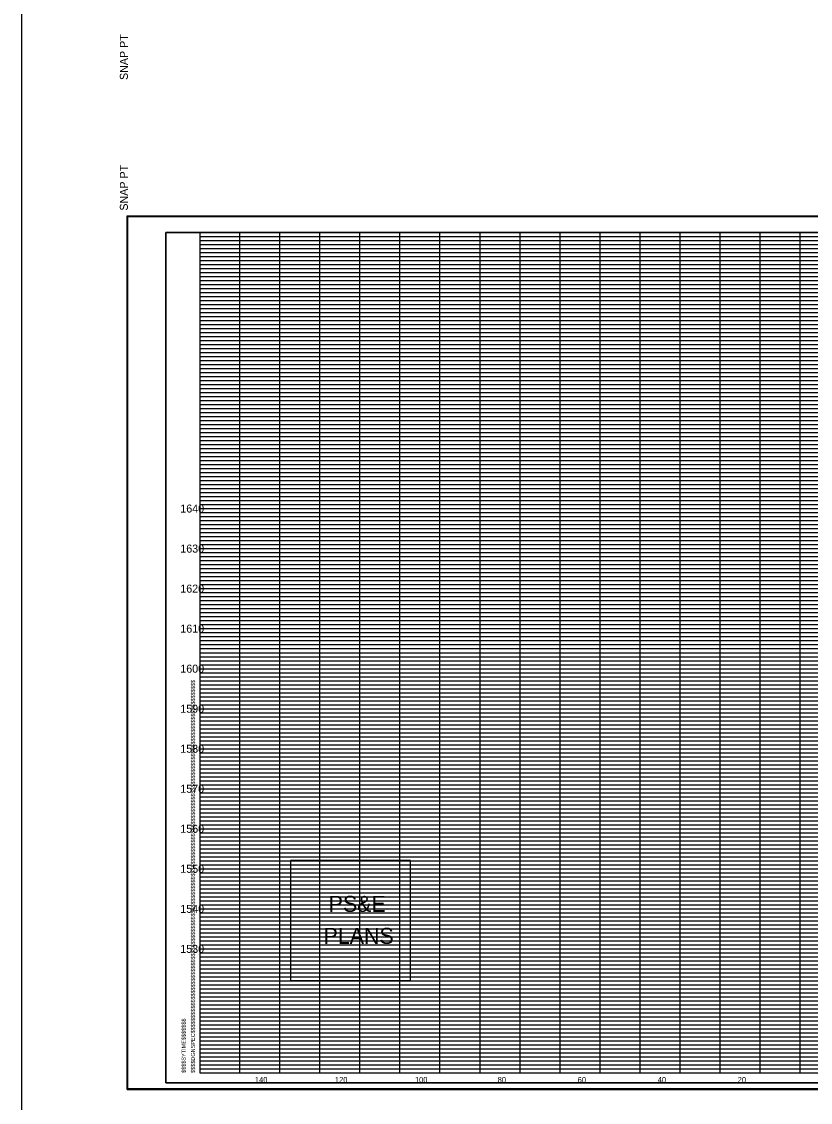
# Model space of a CAD drawing. Extents: x 955 to 1375, y 1248 to 3657.
# Drawn here: x 955.4 to 1152.6, y 2072.7 to 2342.7 of the extents above; entities that cross this region are included whole.
import ezdxf

# ---------------------------------------------------------------- set-up
doc = ezdxf.new("R2010")
doc.units = 0
for name, color, linetype in [('DESIGN - SHEET - Corner Text', 7, 'Continuous'), ('DESIGN - SHEET - Light Grid', 7, 'Continuous'), ('DESIGN - SHEET - Linework', 7, 'Continuous'), ('DESIGN - SHEET - Plot Shape', 7, 'Continuous'), ('DESIGN - TYPICAL - Text', 7, 'Continuous'), ('DESIGN - UTILITIES - Cable (Overhead) with Text', 7, 'Continuous'), ('SURVEY - NON-TRANSPORTATION - Features Text', 7, 'Continuous')]:
    doc.layers.add(name, color=color, linetype=linetype)

# ---------------------------------------------------------------- blocks, each defined once
blk = doc.blocks.new('XSTSHT')
at = {"layer": 'DESIGN - SHEET - Light Grid'}
for p, q in [((0, 20.9), (8, 20.9)), ((0, 20.8), (8, 20.8)), ((8, 20.9), (16, 20.9)), ((8, 20.8), (16, 20.8)), ((0, 20.7), (8, 20.7)), ((0, 20.6), (8, 20.6)), ((8, 20.7), (16, 20.7)), ((8, 20.6), (16, 20.6)), ((0, 20.5), (8, 20.5)), ((0, 20.4), (8, 20.4)), ((0, 20.3), (8, 20.3)), ((8, 20.5), (16, 20.5)), ((8, 20.4), (16, 20.4)), ((8, 20.3), (16, 20.3)), ((0, 20.2), (8, 20.2)), ((0, 20.1), (8, 20.1)), ((8, 20.2), (16, 20.2)), ((8, 20.1), (16, 20.1)), ((0, 19.9), (8, 19.9)), ((0, 19.8), (8, 19.8)), ((8, 19.9), (16, 19.9)), ((8, 19.8), (16, 19.8)), ((0, 19.7), (8, 19.7)), ((0, 19.6), (8, 19.6)), ((0, 19.5), (8, 19.5)), ((8, 19.7), (16, 19.7)), ((8, 19.6), (16, 19.6)), ((8, 19.5), (16, 19.5)), ((0, 19.4), (8, 19.4)), ((0, 19.3), (8, 19.3)), ((0, 19.2), (8, 19.2)), ((8, 19.4), (16, 19.4)), ((8, 19.3), (16, 19.3)), ((8, 19.2), (16, 19.2)), ((0, 19.1), (8, 19.1)), ((0, 18.9), (8, 18.9)), ((8, 19.1), (16, 19.1)), ((8, 18.9), (16, 18.9)), ((0, 18.8), (8, 18.8)), ((0, 18.7), (8, 18.7)), ((8, 18.8), (16, 18.8)), ((8, 18.7), (16, 18.7)), ((0, 18.6), (8, 18.6)), ((0, 18.5), (8, 18.5)), ((0, 18.4), (8, 18.4)), ((8, 18.6), (16, 18.6)), ((8, 18.5), (16, 18.5)), ((8, 18.4), (16, 18.4)), ((0, 18.3), (8, 18.3)), ((0, 18.2), (8, 18.2)), ((0, 18.1), (8, 18.1)), ((8, 18.3), (16, 18.3)), ((8, 18.2), (16, 18.2)), ((8, 18.1), (16, 18.1)), ((0, 17.9), (8, 17.9)), ((8, 17.9), (16, 17.9)), ((0, 17.8), (8, 17.8)), ((0, 17.7), (8, 17.7)), ((0, 17.6), (8, 17.6)), ((8, 17.8), (16, 17.8)), ((8, 17.7), (16, 17.7)), ((8, 17.6), (16, 17.6)), ((0, 17.5), (8, 17.5)), ((0, 17.4), (8, 17.4)), ((0, 17.3), (8, 17.3)), ((8, 17.5), (16, 17.5)), ((8, 17.4), (16, 17.4)), ((8, 17.3), (16, 17.3)), ((0, 17.2), (8, 17.2)), ((0, 17.1), (8, 17.1)), ((8, 17.2), (16, 17.2)), ((8, 17.1), (16, 17.1)), ((0, 16.9), (8, 16.9)), ((0, 16.8), (8, 16.8)), ((8, 16.9), (16, 16.9)), ((8, 16.8), (16, 16.8)), ((0, 16.7), (8, 16.7)), ((0, 16.6), (8, 16.6)), ((0, 16.5), (8, 16.5)), ((8, 16.7), (16, 16.7)), ((8, 16.6), (16, 16.6)), ((8, 16.5), (16, 16.5)), ((0, 16.4), (8, 16.4)), ((0, 16.3), (8, 16.3)), ((8, 16.4), (16, 16.4)), ((8, 16.3), (16, 16.3)), ((0, 16.2), (8, 16.2)), ((0, 16.1), (8, 16.1)), ((8, 16.2), (16, 16.2)), ((8, 16.1), (16, 16.1)), ((0, 15.9), (8, 15.9)), ((0, 15.8), (8, 15.8)), ((0, 15.7), (8, 15.7)), ((8, 15.9), (16, 15.9)), ((8, 15.8), (16, 15.8)), ((8, 15.7), (16, 15.7)), ((0, 15.6), (8, 15.6)), ((0, 15.5), (8, 15.5)), ((0, 15.4), (8, 15.4)), ((8, 15.6), (16, 15.6)), ((8, 15.5), (16, 15.5)), ((8, 15.4), (16, 15.4)), ((0, 15.3), (8, 15.3)), ((0, 15.2), (8, 15.2)), ((8, 15.3), (16, 15.3)), ((8, 15.2), (16, 15.2)), ((0, 15.1), (8, 15.1)), ((0, 14.9), (8, 14.9)), ((8, 15.1), (16, 15.1)), ((8, 14.9), (16, 14.9)), ((0, 14.8), (8, 14.8)), ((0, 14.7), (8, 14.7)), ((0, 14.6), (8, 14.6)), ((8, 14.8), (16, 14.8)), ((8, 14.7), (16, 14.7)), ((8, 14.6), (16, 14.6)), ((0, 14.5), (8, 14.5)), ((0, 14.4), (8, 14.4)), ((8, 14.5), (16, 14.5)), ((8, 14.4), (16, 14.4)), ((0, 14.3), (8, 14.3)), ((0, 14.2), (8, 14.2)), ((0, 14.1), (8, 14.1)), ((8, 14.3), (16, 14.3)), ((8, 14.2), (16, 14.2)), ((8, 14.1), (16, 14.1)), ((0, 13.9), (8, 13.9)), ((0, 13.8), (8, 13.8)), ((8, 13.9), (16, 13.9)), ((8, 13.8), (16, 13.8)), ((0, 13.7), (8, 13.7)), ((0, 13.6), (8, 13.6)), ((0, 13.5), (8, 13.5)), ((8, 13.7), (16, 13.7)), ((8, 13.6), (16, 13.6)), ((8, 13.5), (16, 13.5)), ((0, 13.4), (8, 13.4)), ((0, 13.3), (8, 13.3)), ((8, 13.4), (16, 13.4)), ((8, 13.3), (16, 13.3)), ((0, 13.2), (8, 13.2)), ((0, 13.1), (8, 13.1)), ((8, 13.2), (16, 13.2)), ((8, 13.1), (16, 13.1)), ((0, 12.9), (8, 12.9)), ((0, 12.8), (8, 12.8)), ((0, 12.7), (8, 12.7)), ((8, 12.9), (16, 12.9)), ((8, 12.8), (16, 12.8)), ((8, 12.7), (16, 12.7)), ((0, 12.6), (8, 12.6)), ((0, 12.5), (8, 12.5)), ((8, 12.6), (16, 12.6)), ((8, 12.5), (16, 12.5)), ((0, 12.4), (8, 12.4)), ((0, 12.3), (8, 12.3)), ((0, 12.2), (8, 12.2)), ((8, 12.4), (16, 12.4)), ((8, 12.3), (16, 12.3)), ((8, 12.2), (16, 12.2)), ((0, 12.1), (8, 12.1)), ((0, 11.9), (8, 11.9)), ((8, 12.1), (16, 12.1)), ((8, 11.9), (16, 11.9)), ((0, 11.8), (8, 11.8)), ((0, 11.7), (8, 11.7)), ((8, 11.8), (16, 11.8)), ((8, 11.7), (16, 11.7)), ((0, 11.6), (8, 11.6)), ((0, 11.5), (8, 11.5)), ((0, 11.4), (8, 11.4)), ((8, 11.6), (16, 11.6)), ((8, 11.5), (16, 11.5)), ((8, 11.4), (16, 11.4)), ((0, 11.3), (8, 11.3)), ((0, 11.2), (8, 11.2)), ((0, 11.1), (8, 11.1)), ((8, 11.3), (16, 11.3)), ((8, 11.2), (16, 11.2)), ((8, 11.1), (16, 11.1)), ((0, 10.9), (8, 10.9)), ((0, 10.8), (8, 10.8)), ((8, 10.9), (16, 10.9)), ((8, 10.8), (16, 10.8)), ((0, 10.7), (8, 10.7)), ((0, 10.6), (8, 10.6)), ((8, 10.7), (16, 10.7)), ((8, 10.6), (16, 10.6)), ((0, 10.5), (8, 10.5)), ((0, 10.4), (8, 10.4)), ((0, 10.3), (8, 10.3)), ((8, 10.5), (16, 10.5)), ((8, 10.4), (16, 10.4)), ((8, 10.3), (16, 10.3)), ((0, 10.2), (8, 10.2)), ((0, 10.1), (8, 10.1)), ((8, 10.2), (16, 10.2)), ((8, 10.1), (16, 10.1)), ((0, 9.9), (8, 9.9)), ((0, 9.8), (8, 9.8)), ((8, 9.9), (16, 9.9)), ((8, 9.8), (16, 9.8)), ((0, 9.7), (8, 9.7)), ((0, 9.6), (8, 9.6)), ((0, 9.5), (8, 9.5)), ((8, 9.7), (16, 9.7)), ((8, 9.6), (16, 9.6)), ((8, 9.5), (16, 9.5)), ((0, 9.4), (8, 9.4)), ((0, 9.3), (8, 9.3)), ((0, 9.2), (8, 9.2)), ((8, 9.4), (16, 9.4)), ((8, 9.3), (16, 9.3)), ((8, 9.2), (16, 9.2)), ((0, 9.1), (8, 9.1)), ((8, 9.1), (16, 9.1)), ((0, 8.9), (8, 8.9)), ((0, 8.8), (8, 8.8)), ((0, 8.7), (8, 8.7)), ((8, 8.9), (16, 8.9)), ((8, 8.8), (16, 8.8)), ((8, 8.7), (16, 8.7)), ((0, 8.6), (8, 8.6)), ((0, 8.5), (8, 8.5)), ((0, 8.4), (8, 8.4)), ((8, 8.6), (16, 8.6)), ((8, 8.5), (16, 8.5)), ((8, 8.4), (16, 8.4)), ((0, 8.3), (8, 8.3)), ((0, 8.2), (8, 8.2)), ((8, 8.3), (16, 8.3)), ((8, 8.2), (16, 8.2)), ((0, 8.1), (8, 8.1)), ((0, 7.9), (8, 7.9)), ((8, 8.1), (16, 8.1)), ((8, 7.9), (16, 7.9)), ((0, 7.8), (8, 7.8)), ((0, 7.7), (8, 7.7)), ((0, 7.6), (8, 7.6)), ((8, 7.8), (16, 7.8)), ((8, 7.7), (16, 7.7)), ((8, 7.6), (16, 7.6)), ((0, 7.5), (8, 7.5)), ((0, 7.4), (8, 7.4)), ((0, 7.3), (8, 7.3)), ((8, 7.5), (16, 7.5)), ((8, 7.4), (16, 7.4)), ((8, 7.3), (16, 7.3)), ((0, 7.2), (8, 7.2)), ((0, 7.1), (8, 7.1)), ((8, 7.2), (16, 7.2)), ((8, 7.1), (16, 7.1)), ((0, 6.9), (8, 6.9)), ((0, 6.8), (8, 6.8)), ((8, 6.9), (16, 6.9)), ((8, 6.8), (16, 6.8)), ((0, 6.7), (8, 6.7)), ((0, 6.6), (8, 6.6)), ((0, 6.5), (8, 6.5)), ((8, 6.7), (16, 6.7)), ((8, 6.6), (16, 6.6)), ((8, 6.5), (16, 6.5)), ((0, 6.4), (8, 6.4)), ((0, 6.3), (8, 6.3)), ((8, 6.4), (16, 6.4)), ((8, 6.3), (16, 6.3)), ((0, 6.2), (8, 6.2)), ((0, 6.1), (8, 6.1)), ((8, 6.2), (16, 6.2)), ((8, 6.1), (16, 6.1)), ((0, 5.9), (8, 5.9)), ((0, 5.8), (8, 5.8)), ((0, 5.7), (8, 5.7)), ((8, 5.9), (16, 5.9)), ((8, 5.8), (16, 5.8)), ((8, 5.7), (16, 5.7)), ((0, 5.6), (8, 5.6)), ((0, 5.5), (8, 5.5)), ((0, 5.4), (8, 5.4)), ((8, 5.6), (16, 5.6)), ((8, 5.5), (16, 5.5)), ((8, 5.4), (16, 5.4)), ((0, 5.3), (8, 5.3)), ((0, 5.2), (8, 5.2)), ((8, 5.3), (16, 5.3)), ((8, 5.2), (16, 5.2)), ((0, 5.1), (8, 5.1)), ((0, 4.9), (8, 4.9)), ((8, 5.1), (16, 5.1)), ((8, 4.9), (16, 4.9)), ((0, 4.8), (8, 4.8)), ((0, 4.7), (8, 4.7)), ((0, 4.6), (8, 4.6)), ((8, 4.8), (16, 4.8)), ((8, 4.7), (16, 4.7)), ((8, 4.6), (16, 4.6)), ((0, 4.5), (8, 4.5)), ((0, 4.4), (8, 4.4)), ((8, 4.5), (16, 4.5)), ((8, 4.4), (16, 4.4)), ((0, 4.3), (8, 4.3)), ((0, 4.2), (8, 4.2)), ((0, 4.1), (8, 4.1)), ((8, 4.3), (16, 4.3)), ((8, 4.2), (16, 4.2)), ((8, 4.1), (16, 4.1)), ((0, 3.9), (8, 3.9)), ((0, 3.8), (8, 3.8)), ((8, 3.9), (16, 3.9)), ((8, 3.8), (16, 3.8)), ((0, 3.7), (8, 3.7)), ((0, 3.6), (8, 3.6)), ((8, 3.7), (16, 3.7)), ((8, 3.6), (16, 3.6)), ((0, 3.5), (8, 3.5)), ((0, 3.4), (8, 3.4)), ((0, 3.3), (8, 3.3)), ((8, 3.5), (16, 3.5)), ((8, 3.4), (16, 3.4)), ((8, 3.3), (16, 3.3)), ((0, 3.2), (8, 3.2)), ((0, 3.1), (8, 3.1)), ((8, 3.2), (16, 3.2)), ((8, 3.1), (16, 3.1)), ((0, 2.9), (8, 2.9)), ((0, 2.8), (8, 2.8)), ((0, 2.7), (8, 2.7)), ((8, 2.9), (16, 2.9)), ((8, 2.8), (16, 2.8)), ((8, 2.7), (16, 2.7)), ((0, 2.6), (8, 2.6)), ((0, 2.5), (8, 2.5)), ((8, 2.6), (16, 2.6)), ((8, 2.5), (16, 2.5)), ((0, 2.4), (8, 2.4)), ((0, 2.3), (8, 2.3)), ((0, 2.2), (8, 2.2)), ((8, 2.4), (16, 2.4)), ((8, 2.3), (16, 2.3)), ((8, 2.2), (16, 2.2)), ((0, 2.1), (8, 2.1)), ((0, 1.9), (8, 1.9)), ((8, 2.1), (16, 2.1)), ((8, 1.9), (16, 1.9)), ((0, 1.8), (8, 1.8)), ((0, 1.7), (8, 1.7)), ((8, 1.8), (16, 1.8)), ((8, 1.7), (16, 1.7)), ((0, 1.6), (8, 1.6)), ((0, 1.5), (8, 1.5)), ((0, 1.4), (8, 1.4)), ((8, 1.6), (16, 1.6)), ((8, 1.5), (16, 1.5)), ((8, 1.4), (16, 1.4)), ((0, 1.3), (8, 1.3)), ((0, 1.2), (8, 1.2)), ((0, 1.1), (8, 1.1)), ((8, 1.3), (16, 1.3)), ((8, 1.2), (16, 1.2)), ((8, 1.1), (16, 1.1)), ((0, 0.9), (8, 0.9)), ((8, 0.9), (16, 0.9)), ((0, 0.8), (8, 0.8)), ((0, 0.7), (8, 0.7)), ((0, 0.6), (8, 0.6)), ((8, 0.8), (16, 0.8)), ((8, 0.7), (16, 0.7)), ((8, 0.6), (16, 0.6)), ((0, 0.5), (8, 0.5)), ((0, 0.4), (8, 0.4)), ((0, 0.3), (8, 0.3)), ((8, 0.5), (16, 0.5)), ((8, 0.4), (16, 0.4)), ((8, 0.3), (16, 0.3)), ((0, 0.2), (8, 0.2)), ((0, 0.1), (8, 0.1)), ((8, 0.2), (16, 0.2)), ((8, 0.1), (16, 0.1))]:
    blk.add_line(p, q, dxfattribs=at)
at = {"layer": 'DESIGN - SHEET - Linework'}
for p, q in [((-1.823, -0.414), (-1.823, 21.414)), ((-1.823, 21.414), (32.217, 21.414)), ((1, 0), (1, 21)), ((2, 0), (2, 21)), ((3, 0), (3, 21)), ((4, 0), (4, 21)), ((5, 0), (5, 21)), ((6, 0), (6, 21)), ((7, 0), (7, 21)), ((8, 0), (8, 21)), ((9, 0), (9, 21)), ((10, 0), (10, 21)), ((11, 0), (11, 21)), ((12, 0), (12, 21)), ((13, 0), (13, 21)), ((14, 0), (14, 21)), ((15, 0), (15, 21)), ((0, 20), (28, 20)), ((0, 19), (32, 19)), ((0, 18), (32, 18)), ((0, 17), (32, 17)), ((0, 16), (32, 16)), ((0, 15), (32, 15)), ((0, 14), (32, 14)), ((0, 13), (32, 13)), ((0, 12), (32, 12)), ((0, 11), (32, 11)), ((0, 10), (32, 10)), ((0, 9), (32, 9)), ((0, 8), (32, 8)), ((0, 7), (32, 7)), ((0, 6), (32, 6)), ((0, 5), (32, 5)), ((0, 4), (32, 4)), ((0, 3), (32, 3)), ((0, 2), (32, 2)), ((0, 1), (32, 1)), ((-1.823, -0.414), (32.217, -0.414))]:
    blk.add_line(p, q, dxfattribs=at)
blk.add_lwpolyline([(0, 21), (0, 0), (32, 0), (32, 21), (0, 21)], dxfattribs=at)
at = {"layer": 'DESIGN - SHEET - Plot Shape'}
for points in [[(-1.803, 21.394), (32.197, 21.394), (32.197, -0.394), (-1.803, -0.394)], [(-0.85, 21), (32, 21), (32, -0.25), (-0.85, -0.25)]]:
    blk.add_lwpolyline(points, close=True, dxfattribs=at)
at = {"layer": 'DESIGN - SHEET - Corner Text'}
for s, height, p in [('  SNAP PT', 0.2, (-1.803, 21.394)), ('$$$$DGNSPEC$$$$$$$$$$$$$$$$$$$$$$$$$$$$$$$$$$$$$$$$$$$$$$$$$$$$$$$$$$$$$$$$$$$$$$$$$$$$$$$$$$$$$$$$$$$$$$$$$$$$$$$$$$$$$$$$$$$', 0.100002, (-0.126, 0)), ('$$$$SYTIME$$$$$$$', 0.1, (-0.358, 0)), ('SNAP PT  ', 0.2, (-1.803, -2.194))]:
    blk.add_text(s, height=height, rotation=90, dxfattribs=at).set_placement(p)

msp = doc.modelspace()

# ---------------------------------------------------------------- linework, layer by layer
at = {"layer": 'DESIGN - SHEET - Corner Text'}
msp.add_lwpolyline([(1022.65, 2133.08), (1022.65, 2103.08), (1052.65, 2103.08), (1052.65, 2133.08)], close=True, dxfattribs=at)
at = {"layer": 'DESIGN - SHEET - Plot Shape'}
msp.add_lwpolyline([(991.5, 2077.5), (1320, 2077.5), (1320, 2290), (991.5, 2290)], close=True, dxfattribs=at)
at = {"layer": 'SURVEY - NON-TRANSPORTATION - Features Text'}
msp.add_lwpolyline([(955.41, 1505.76), (1344.98, 1505.76), (1344.98, 3398.01), (955.41, 3398.01)], close=True, dxfattribs=at)

# ---------------------------------------------------------------- block references
at = {"layer": 'DESIGN - UTILITIES - Cable (Overhead) with Text', "xscale": 10, "yscale": 10}
for p in [(1000, 2350), (1000, 2080)]:
    msp.add_blockref('XSTSHT', p, dxfattribs=at)

# ---------------------------------------------------------------- texts
at = {"layer": 'DESIGN - SHEET - Corner Text'}
for s, p in [('PS&E', (1032.17, 2120.25)), ('PLANS', (1030.89, 2112.25))]:
    msp.add_text(s, height=4, dxfattribs=at).set_placement(p)
at = {"layer": 'DESIGN - TYPICAL - Text'}
for s, height, p in [('     1640     ', 2, (991.37, 2220)), ('     1630     ', 2, (991.37, 2210)), ('     1620     ', 2, (991.37, 2200)), ('     1610     ', 2, (991.37, 2190)), ('     1600     ', 2, (991.37, 2180)), ('     1590     ', 2, (991.37, 2170)), ('     1580     ', 2, (991.37, 2160)), ('     1570     ', 2, (991.37, 2150)), ('     1560     ', 2, (991.37, 2140)), ('     1550     ', 2, (991.37, 2130)), ('     1540     ', 2, (991.37, 2120)), ('     1530     ', 2, (991.37, 2110)), ('     140     ', 1.4, (1011.14, 2077.6)), ('     120     ', 1.4, (1031.14, 2077.6)), ('     100     ', 1.4, (1051.14, 2077.6)), ('     80     ', 1.4, (1071.82, 2077.6)), ('     60     ', 1.4, (1091.82, 2077.6)), ('     40     ', 1.4, (1111.82, 2077.6)), ('     20     ', 1.4, (1131.82, 2077.6))]:
    msp.add_text(s, height=height, dxfattribs=at).set_placement(p)

doc.saveas('drawing.dxf')
